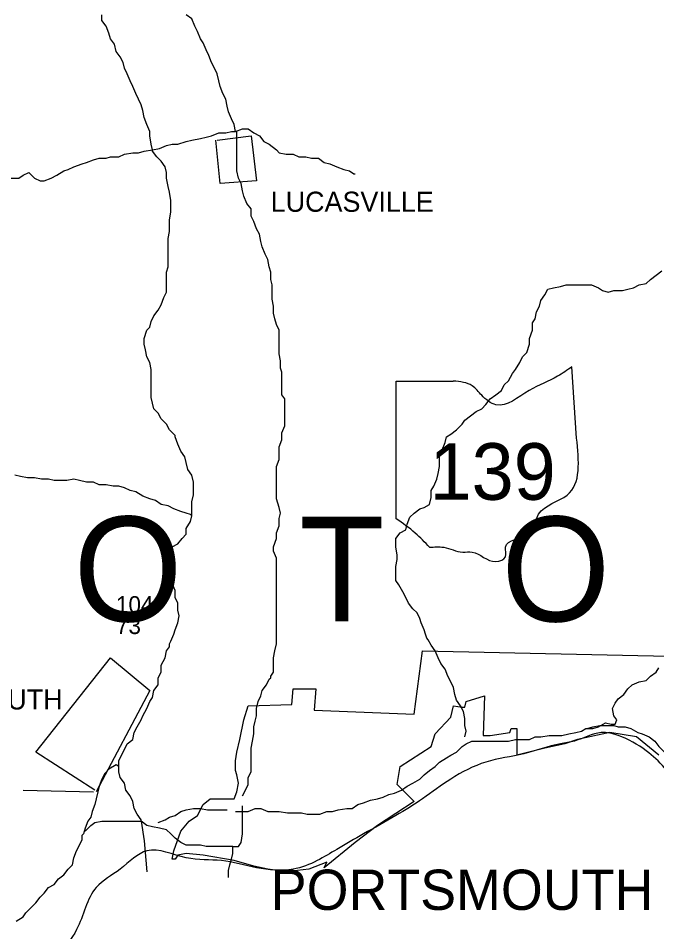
# Model space of a CAD drawing. Extents: x 0 to 34, y 0 to 22.
# Drawn here: x 5.85 to 6.469, y 16.374 to 17.259 of the extents above; entities that cross this region are included whole.
import ezdxf

# ---------------------------------------------------------------- set-up
doc = ezdxf.new("R2010")
doc.units = 0
doc.layers.add('Default', color=7, linetype='Continuous')
doc.layers.add('TR_Turning_Path1', color=7, linetype='Continuous')

msp = doc.modelspace()

# ---------------------------------------------------------------- linework, layer by layer
at = {"layer": 'Default'}
msp.add_line((5.85492, 16.51101), (5.92309, 16.50964), dxfattribs=at)
for points in [[(5.9749, 17.1559), (5.97217, 17.16272), (5.97081, 17.16954), (5.96944, 17.17499), (5.96672, 17.18045), (5.96399, 17.1859), (5.96126, 17.19272), (5.95854, 17.19817), (5.95581, 17.20499), (5.95308, 17.21044), (5.95172, 17.2159), (5.94899, 17.22135), (5.9449, 17.2268), (5.94354, 17.23362), (5.93945, 17.23907), (5.93809, 17.24453), (5.93536, 17.25134), (5.93127, 17.2568), (5.93127, 17.26225)], [(6.06079, 17.14909), (6.05943, 17.1559), (6.0567, 17.16136), (6.05398, 17.16818), (6.05261, 17.17363), (6.05125, 17.18045), (6.04852, 17.1859), (6.0458, 17.19272), (6.04443, 17.19817), (6.04307, 17.20499), (6.04034, 17.21044), (6.03762, 17.2159), (6.03489, 17.22271), (6.03216, 17.22817), (6.02944, 17.23498), (6.02671, 17.23907), (6.02398, 17.24589), (6.02125, 17.25134), (6.01853, 17.25816), (6.01307, 17.26225)], [(5.98035, 17.13136), (5.97899, 17.13682), (5.97763, 17.145), (5.97763, 17.14909), (5.9749, 17.1559), (5.9749, 17.1559)], [(5.98035, 17.13136), (5.98717, 17.13273), (5.99399, 17.13545), (5.99944, 17.13682), (6.00489, 17.13682), (6.01307, 17.13954), (6.01853, 17.14091), (6.02671, 17.14227), (6.03216, 17.14363), (6.03762, 17.145), (6.04443, 17.14772), (6.05125, 17.14772), (6.0567, 17.14909), (6.06079, 17.14909)], [(6.06079, 17.14909), (6.06761, 17.15181), (6.07306, 17.15181), (6.07852, 17.14772), (6.08397, 17.145), (6.08806, 17.13954), (6.09352, 17.13682), (6.10033, 17.13136), (6.10306, 17.12864), (6.10988, 17.12727), (6.11669, 17.12727), (6.12215, 17.12455), (6.12896, 17.12455), (6.13442, 17.12318), (6.14124, 17.12318), (6.14669, 17.11909), (6.15214, 17.11773), (6.15896, 17.115), (6.16578, 17.11228), (6.17123, 17.11091), (6.17532, 17.10818), (6.17668, 17.10818)], [(6.10306, 16.95003), (6.10306, 16.95685), (6.10033, 16.9623), (6.09897, 16.96775), (6.09761, 16.97321), (6.09761, 16.98002), (6.09624, 16.98684), (6.09624, 16.99366), (6.09624, 17.00047), (6.09488, 17.00593), (6.09488, 17.01275), (6.09352, 17.0182), (6.09215, 17.02502), (6.08943, 17.03047), (6.0867, 17.03729), (6.08534, 17.04274), (6.08397, 17.04956), (6.08125, 17.05501), (6.07852, 17.06183), (6.07579, 17.06728), (6.07579, 17.0741), (6.0717, 17.07955), (6.06897, 17.08637), (6.06761, 17.09182), (6.06625, 17.09864), (6.06352, 17.10409), (6.06216, 17.11091), (6.06216, 17.115), (6.06216, 17.12318), (6.06216, 17.12864), (6.06216, 17.13545), (6.06216, 17.14227), (6.06216, 17.14772), (6.06216, 17.14909), (6.06079, 17.14909)], [(6.04307, 17.14091), (6.07579, 17.145), (6.08125, 17.10137), (6.0458, 17.09864), (6.04171, 17.14091)], [(5.84265, 17.10409), (5.85083, 17.10409), (5.85492, 17.10682), (5.86037, 17.10955), (5.86582, 17.10409), (5.87128, 17.10137), (5.87537, 17.10137), (5.88219, 17.10409), (5.88764, 17.10682), (5.89446, 17.11091), (5.89855, 17.11228), (5.904, 17.115), (5.91218, 17.11773), (5.91627, 17.11909), (5.92309, 17.12182), (5.92854, 17.12318), (5.93536, 17.12318), (5.93945, 17.12455), (5.94763, 17.12455), (5.95308, 17.12727), (5.96126, 17.12864), (5.96672, 17.12864), (5.97217, 17.13), (5.98035, 17.13136), (5.98035, 17.13136)], [(5.97763, 16.95957), (5.97899, 16.96503), (5.98172, 16.97048), (5.98581, 16.97593), (5.98853, 16.98139), (5.99126, 16.9882), (5.99399, 16.99366), (5.99399, 17.00047), (5.99399, 17.00593), (5.99399, 17.01275), (5.99535, 17.0182), (5.99535, 17.02502), (5.99535, 17.03183), (5.99535, 17.03865), (5.99535, 17.04547), (5.99671, 17.05228), (5.99671, 17.05774), (5.99671, 17.06319), (5.99808, 17.07137), (5.99808, 17.07819), (5.99808, 17.08228), (5.99671, 17.09046), (5.99535, 17.09591), (5.99399, 17.10409), (5.99399, 17.10955), (5.99262, 17.115), (5.98853, 17.12046), (5.98444, 17.12455), (5.98035, 17.13), (5.98035, 17.13136), (5.98035, 17.13136)], [(6.4221, 16.99366), (6.42755, 16.99502), (6.43573, 16.99502), (6.44119, 16.99638), (6.44664, 16.99775), (6.4521, 17.00047), (6.45891, 17.00184), (6.463, 17.00593), (6.46846, 17.01002), (6.47391, 17.01411)], [(6.34575, 16.94321), (6.34575, 16.94866), (6.34848, 16.95685), (6.34848, 16.96366), (6.3512, 16.96775), (6.35257, 16.97457), (6.35529, 16.98002), (6.35666, 16.98548), (6.36075, 16.99093), (6.36347, 16.99638), (6.36893, 16.99775), (6.37574, 16.99911), (6.3812, 17.00047), (6.38801, 17.00047), (6.39483, 17.00047), (6.40029, 17.00047), (6.40574, 17.00047), (6.41256, 16.99775), (6.41665, 16.99502), (6.4221, 16.99366), (6.4221, 16.99366)], [(6.00217, 16.85459), (5.99671, 16.86004), (5.99399, 16.8655), (5.98853, 16.87095), (5.98581, 16.8764), (5.98172, 16.88049), (5.98035, 16.88595), (5.97899, 16.8914), (5.97899, 16.89958), (5.97899, 16.9064), (5.97899, 16.91185), (5.97899, 16.91867), (5.97763, 16.92549), (5.9749, 16.93094), (5.97353, 16.93776), (5.97217, 16.94321), (5.97217, 16.94866), (5.9749, 16.95685), (5.97763, 16.95957)], [(6.10033, 16.79323), (6.10033, 16.80005), (6.10033, 16.80551), (6.10033, 16.81232), (6.10033, 16.81778), (6.10033, 16.82459), (6.10306, 16.83141), (6.10306, 16.83686), (6.10306, 16.84368), (6.10579, 16.8505), (6.10579, 16.85732), (6.10851, 16.86413), (6.10851, 16.86959), (6.10851, 16.87504), (6.10851, 16.88322), (6.10851, 16.89004), (6.10579, 16.89413), (6.10579, 16.90231), (6.10579, 16.90776), (6.10579, 16.91594), (6.10442, 16.92003), (6.10442, 16.92685), (6.10306, 16.93367), (6.10306, 16.94048), (6.10306, 16.9473), (6.10306, 16.94866), (6.10306, 16.95003)], [(6.26122, 16.84095), (6.26394, 16.84777), (6.26531, 16.85323), (6.2694, 16.85595), (6.27485, 16.86004), (6.2803, 16.8655), (6.28303, 16.86959), (6.28849, 16.87368), (6.29394, 16.87777), (6.29939, 16.88049), (6.30348, 16.88458), (6.30757, 16.89004), (6.31303, 16.89413), (6.31848, 16.89822), (6.32121, 16.90367), (6.3253, 16.90776), (6.32939, 16.91458), (6.33211, 16.91867), (6.3362, 16.92549), (6.33893, 16.93094), (6.34302, 16.93503), (6.34575, 16.94321), (6.34575, 16.94321)], [(6.39142, 16.8522), (6.38682, 16.92123)], [(6.21656, 16.77398), (6.21656, 16.90742), (6.27178, 16.90742)], [(6.01853, 16.77687), (6.01853, 16.78369), (6.01853, 16.79051), (6.01989, 16.79733), (6.01989, 16.80414), (6.01989, 16.8096), (6.01853, 16.81641), (6.01444, 16.82187), (6.01307, 16.82868), (6.01171, 16.83414), (6.00762, 16.83959), (6.00489, 16.84641), (6.00217, 16.85323), (6.00217, 16.85323), (6.00217, 16.85459)], [(6.21622, 16.75506), (6.22031, 16.76051), (6.22577, 16.76324), (6.22713, 16.76869), (6.22986, 16.77551), (6.23395, 16.7796), (6.2394, 16.78369), (6.24349, 16.78505), (6.24895, 16.78778), (6.25031, 16.7946), (6.25031, 16.80142), (6.25304, 16.80551), (6.25576, 16.81232), (6.25713, 16.81778), (6.25849, 16.82459), (6.25849, 16.82868), (6.25849, 16.83686), (6.26122, 16.83959), (6.26122, 16.84095)], [(6.01853, 16.77687), (6.01716, 16.77824), (6.01307, 16.7796), (6.00762, 16.78096), (6.0008, 16.78369), (5.99535, 16.78642), (5.98853, 16.78778), (5.98308, 16.79187), (5.97763, 16.79323), (5.97081, 16.79596), (5.96399, 16.80005), (5.95854, 16.80142), (5.95308, 16.80414), (5.94763, 16.80551), (5.94218, 16.80551), (5.93536, 16.80687), (5.92854, 16.80687), (5.92309, 16.8096), (5.91627, 16.8096), (5.90945, 16.81096), (5.904, 16.81232), (5.89718, 16.81096), (5.89037, 16.81096), (5.88491, 16.81096), (5.87946, 16.81232), (5.87264, 16.81232), (5.86582, 16.81369), (5.85901, 16.81369), (5.85219, 16.81505), (5.84674, 16.81641)], [(6.09488, 16.62144), (6.09761, 16.62553), (6.09761, 16.63235), (6.09761, 16.63917), (6.09897, 16.64599), (6.10033, 16.6528), (6.10033, 16.65826), (6.10033, 16.66507), (6.10033, 16.67053), (6.10033, 16.67734), (6.10033, 16.68416), (6.10033, 16.68961), (6.10033, 16.6978), (6.10033, 16.70325), (6.10033, 16.71007), (6.10033, 16.71416), (6.10033, 16.72234), (6.10033, 16.72779), (6.10033, 16.73597), (6.09761, 16.74279), (6.09761, 16.74688), (6.10033, 16.75506), (6.10033, 16.76051), (6.10306, 16.76733), (6.10306, 16.77415), (6.10442, 16.7796), (6.10306, 16.78505), (6.10033, 16.79323)], [(5.99671, 16.65008), (5.99671, 16.6528), (5.99808, 16.65553), (6.0008, 16.66235), (6.00217, 16.66644), (6.00489, 16.67325), (6.00626, 16.68007), (6.00489, 16.68552), (6.00489, 16.69234), (6.00217, 16.6978), (6.00217, 16.70461), (5.99944, 16.71143), (5.99808, 16.71688), (5.99671, 16.72234), (5.99535, 16.72915), (5.99535, 16.73597), (5.99535, 16.74279), (5.99944, 16.74688), (6.00489, 16.74961), (6.00898, 16.75506), (6.01307, 16.75915), (6.01307, 16.7646), (6.01716, 16.77142), (6.01853, 16.77687)], [(5.99671, 16.65008), (5.99671, 16.6528), (5.99808, 16.65553), (6.0008, 16.66235), (6.00217, 16.66644), (6.00489, 16.67325), (6.00626, 16.68007), (6.00489, 16.68552), (6.00489, 16.69234), (6.00217, 16.6978), (6.00217, 16.70461), (5.99944, 16.71143), (5.99808, 16.71688), (5.99671, 16.72234), (5.99535, 16.72915), (5.99535, 16.73597), (5.99535, 16.74279), (5.99944, 16.74688), (6.00489, 16.74961), (6.00898, 16.75506), (6.01307, 16.75915), (6.01307, 16.7646), (6.01716, 16.77142), (6.01853, 16.77687)], [(6.24486, 16.66235), (6.24349, 16.66644), (6.24077, 16.67325), (6.2394, 16.67734), (6.23668, 16.6828), (6.23258, 16.68689), (6.22849, 16.69234), (6.22577, 16.6978), (6.22304, 16.70325), (6.21895, 16.71007), (6.21622, 16.71416), (6.21622, 16.72097), (6.21622, 16.72779), (6.21759, 16.73461), (6.21759, 16.7387), (6.21622, 16.74688), (6.21622, 16.75233), (6.21622, 16.75506)], [(6.28303, 16.56282), (6.28439, 16.56827), (6.28303, 16.57372), (6.28303, 16.58054), (6.28167, 16.58736), (6.27894, 16.59281), (6.27485, 16.59827), (6.27349, 16.60372), (6.27212, 16.61054), (6.2694, 16.61599), (6.26667, 16.62144), (6.26394, 16.62826), (6.25985, 16.63371), (6.25713, 16.63917), (6.2544, 16.64599), (6.25031, 16.65144), (6.24758, 16.65689), (6.24622, 16.65826), (6.24486, 16.66235)], [(5.94763, 16.53418), (5.94763, 16.53555), (5.94763, 16.53964), (5.95036, 16.54509), (5.95308, 16.55055), (5.95581, 16.556), (5.96126, 16.56009), (5.96263, 16.56691), (5.96535, 16.57236), (5.96944, 16.57918), (5.97081, 16.58327), (5.9749, 16.59009), (5.97763, 16.5969), (5.98035, 16.60099), (5.98172, 16.60781), (5.98581, 16.61326), (5.98581, 16.62008), (5.98853, 16.62553), (5.98853, 16.63235), (5.99262, 16.63917), (5.99399, 16.64599), (5.99671, 16.65008)], [(5.94763, 16.53418), (5.94763, 16.53555), (5.94763, 16.53964), (5.95036, 16.54509), (5.95308, 16.55055), (5.95581, 16.556), (5.96126, 16.56009), (5.96263, 16.56691), (5.96535, 16.57236), (5.96944, 16.57918), (5.97081, 16.58327), (5.9749, 16.59009), (5.97763, 16.5969), (5.98035, 16.60099), (5.98172, 16.60781), (5.98581, 16.61326), (5.98581, 16.62008), (5.98853, 16.62553), (5.98853, 16.63235), (5.99262, 16.63917), (5.99399, 16.64599), (5.99671, 16.65008)], [(6.0008, 16.45238), (6.00762, 16.47147), (6.0158, 16.48101), (6.02398, 16.48647), (6.02944, 16.49737), (6.03625, 16.50283), (6.05943, 16.50283), (6.06216, 16.50964), (6.06352, 16.51782), (6.06216, 16.526), (6.06079, 16.53009), (6.06079, 16.53964), (6.06216, 16.54782), (6.06488, 16.56009), (6.06897, 16.57918), (6.07306, 16.59281), (6.11533, 16.59418), (6.11669, 16.60917), (6.13851, 16.60917), (6.13715, 16.58872), (6.23395, 16.58463), (6.24213, 16.64599), (6.49573, 16.64053)], [(5.92445, 16.51101), (5.86719, 16.54782), (5.93945, 16.63917), (5.97763, 16.60781), (5.92582, 16.50964)], [(6.42892, 16.57509), (6.43028, 16.57918), (6.42755, 16.58327), (6.42619, 16.59009), (6.42892, 16.59554), (6.43164, 16.59963), (6.4371, 16.60372), (6.44119, 16.60917), (6.44528, 16.61326), (6.4521, 16.61599), (6.45891, 16.61735), (6.463, 16.62144), (6.46846, 16.62553), (6.47118, 16.62962)], [(6.07579, 16.53282), (6.07579, 16.53964), (6.07579, 16.54646), (6.07579, 16.55191), (6.07715, 16.55873), (6.07852, 16.56554), (6.07852, 16.57236), (6.07988, 16.57781), (6.08125, 16.58327), (6.08125, 16.59009), (6.08261, 16.5969), (6.08534, 16.60236), (6.0867, 16.60781), (6.09079, 16.61326), (6.09352, 16.61872), (6.09488, 16.62008), (6.09488, 16.62144)], [(6.23395, 16.5001), (6.21759, 16.51646), (6.22031, 16.53418), (6.25031, 16.55327), (6.2544, 16.56554), (6.2694, 16.5819), (6.27212, 16.59281), (6.2803, 16.59145), (6.28303, 16.59145), (6.28439, 16.5969), (6.30212, 16.60236), (6.30076, 16.56418), (6.30757, 16.56418), (6.32666, 16.56691), (6.32802, 16.571), (6.33348, 16.571), (6.33348, 16.54509)], [(6.40165, 16.571), (6.4071, 16.571), (6.41256, 16.57236), (6.41937, 16.57645), (6.42483, 16.57509), (6.42892, 16.57509)], [(6.40165, 16.571), (6.4071, 16.57236), (6.41392, 16.57372), (6.41937, 16.57372), (6.42755, 16.57372), (6.43164, 16.57236), (6.43846, 16.57236), (6.44392, 16.571), (6.45073, 16.56691), (6.45482, 16.56554), (6.46164, 16.56282), (6.46709, 16.55873), (6.47118, 16.55327), (6.47664, 16.54782), (6.47664, 16.54782)], [(6.31303, 16.55873), (6.31848, 16.55873), (6.3253, 16.55873), (6.33211, 16.56009), (6.33893, 16.56009), (6.34575, 16.56009), (6.3512, 16.56282), (6.35666, 16.56282), (6.36484, 16.56418), (6.37029, 16.56418), (6.37711, 16.56418), (6.38392, 16.56554), (6.39074, 16.56691), (6.3962, 16.56827), (6.40029, 16.571), (6.40165, 16.571)], [(6.47118, 16.54509), (6.44937, 16.56282), (6.42346, 16.56691), (6.39211, 16.56009), (6.37983, 16.556), (6.36075, 16.55191), (6.33348, 16.54509)], [(6.19168, 16.50146), (6.1985, 16.50283), (6.20395, 16.50419), (6.20941, 16.50692), (6.21486, 16.50828), (6.22168, 16.51101), (6.22713, 16.5151), (6.23258, 16.51782), (6.2394, 16.52191), (6.24349, 16.526), (6.24895, 16.53009), (6.2544, 16.53418), (6.25849, 16.53828), (6.26531, 16.54237), (6.2694, 16.54509), (6.27485, 16.54782), (6.2803, 16.55327), (6.28439, 16.556), (6.28985, 16.55873), (6.28985, 16.55873)], [(6.28985, 16.55873), (6.29667, 16.55873), (6.30348, 16.55873), (6.3103, 16.55873), (6.31303, 16.55873)], [(5.94763, 16.53418), (5.94763, 16.53418), (5.9449, 16.53555), (5.93809, 16.53146), (5.934, 16.52737), (5.93127, 16.52191), (5.92854, 16.5151), (5.92718, 16.50964), (5.92582, 16.50283), (5.92445, 16.49737), (5.92172, 16.49056), (5.92036, 16.4851)], [(5.96944, 16.48101), (5.96944, 16.48237), (5.96535, 16.48783), (5.96263, 16.49328), (5.96126, 16.5001), (5.95854, 16.50555), (5.95445, 16.51101), (5.95308, 16.51782), (5.94899, 16.52328), (5.94763, 16.52873), (5.94763, 16.53418)], [(5.96944, 16.48101), (5.96944, 16.48237), (5.96535, 16.48783), (5.96263, 16.49328), (5.96126, 16.5001), (5.95854, 16.50555), (5.95445, 16.51101), (5.95308, 16.51782), (5.94899, 16.52328), (5.94763, 16.52873), (5.94763, 16.53418)], [(6.06761, 16.50555), (6.07034, 16.51101), (6.07306, 16.51646), (6.07306, 16.52328), (6.07579, 16.52873), (6.07579, 16.53282)], [(6.23395, 16.5001), (6.1985, 16.47692), (6.17668, 16.46056), (6.14669, 16.43602), (6.14942, 16.44147), (6.13169, 16.43466), (6.10988, 16.43193), (6.09215, 16.43466), (6.07852, 16.43738), (6.05943, 16.44284), (6.02944, 16.44829), (6.01307, 16.44965), (6.00489, 16.44829), (6.00217, 16.4442)], [(6.06761, 16.49056), (6.06761, 16.49601)], [(6.15487, 16.49056), (6.16032, 16.49192), (6.1685, 16.49328), (6.17396, 16.49328), (6.17941, 16.49737), (6.18487, 16.49874), (6.19168, 16.50146)], [(5.92036, 16.4851), (5.91763, 16.48101), (5.91491, 16.47419), (5.91354, 16.46874)], [(5.98581, 16.47965), (5.99262, 16.48237), (5.99671, 16.4851), (6.00217, 16.48647), (6.00762, 16.49056), (6.01307, 16.49192), (6.01989, 16.49328), (6.02671, 16.49328), (6.03353, 16.49192), (6.03898, 16.49192), (6.0458, 16.49192), (6.05125, 16.49192), (6.05261, 16.49192)], [(6.05807, 16.45647), (6.06352, 16.45647), (6.06625, 16.46056), (6.06761, 16.46874), (6.06761, 16.47419), (6.06761, 16.48101), (6.06761, 16.48647), (6.06761, 16.49056)], [(6.06079, 16.49056), (6.06761, 16.49056), (6.06761, 16.49056)], [(6.06761, 16.49056), (6.07306, 16.49056), (6.07988, 16.49328), (6.08534, 16.49328), (6.09215, 16.49056), (6.09761, 16.49056), (6.10306, 16.49056), (6.11124, 16.48919), (6.11669, 16.48919), (6.12487, 16.48919), (6.13033, 16.48783), (6.13715, 16.48783), (6.1426, 16.48783), (6.14942, 16.49056), (6.15214, 16.49056), (6.15487, 16.49056)], [(5.91491, 16.47147), (5.92036, 16.47692), (5.92445, 16.47965), (5.93127, 16.48101), (5.93809, 16.48101), (5.9449, 16.48101), (5.94899, 16.48101), (5.95581, 16.48101), (5.96263, 16.48101), (5.96944, 16.48101), (5.96944, 16.48101)], [(6.05807, 16.45647), (6.0567, 16.45647), (6.05261, 16.45647), (6.0458, 16.45647), (6.03898, 16.45647), (6.03216, 16.45647), (6.02671, 16.45783), (6.01989, 16.45783), (6.01307, 16.45783), (6.00762, 16.46056), (6.00217, 16.46465), (5.99808, 16.46874), (5.99399, 16.47283), (5.98717, 16.47419), (5.98035, 16.47556), (5.9749, 16.47692), (5.96944, 16.48101)], [(6.05807, 16.45647), (6.0567, 16.45647), (6.05261, 16.45647), (6.0458, 16.45647), (6.03898, 16.45647), (6.03216, 16.45647), (6.02671, 16.45783), (6.01989, 16.45783), (6.01307, 16.45783), (6.00762, 16.46056), (6.00217, 16.46465), (5.99808, 16.46874), (5.99399, 16.47283), (5.98717, 16.47419), (5.98035, 16.47556), (5.9749, 16.47692), (5.96944, 16.48101)], [(5.96944, 16.48101), (5.97217, 16.46192), (5.9749, 16.43193)], [(5.8481, 16.38421), (5.85492, 16.3883), (5.85764, 16.39239), (5.8631, 16.39784), (5.86719, 16.40193), (5.87128, 16.40739), (5.87537, 16.41148), (5.87946, 16.41693), (5.88491, 16.41966), (5.889, 16.42511), (5.89446, 16.4292), (5.89855, 16.43466), (5.90264, 16.43875), (5.904, 16.44556), (5.90673, 16.45238), (5.90945, 16.45783), (5.91218, 16.46329), (5.91218, 16.46738), (5.91354, 16.46874)], [(6.00217, 16.4442), (5.99944, 16.4442), (6.0008, 16.45238)], [(6.0567, 16.4442), (6.05807, 16.44965), (6.05807, 16.45647)], [(6.05398, 16.42647), (6.05398, 16.43329), (6.05534, 16.43875), (6.0567, 16.4442), (6.0567, 16.4442)]]:
    msp.add_lwpolyline(points, dxfattribs=at)
for points in [[(6.38682, 16.92123), (6.37302, 16.91202), (6.34541, 16.89822), (6.3132, 16.88441), (6.29939, 16.89362), (6.29019, 16.90282), (6.27178, 16.90742)], [(6.24878, 16.74637), (6.26258, 16.74637), (6.28099, 16.74177), (6.29019, 16.74177), (6.3132, 16.73256), (6.3224, 16.73716), (6.3224, 16.74637), (6.34541, 16.76017), (6.35461, 16.77858), (6.38222, 16.79698), (6.39142, 16.8522)], [(6.24878, 16.74637), (6.23497, 16.76017), (6.21656, 16.77398)], [(6.69478, 15.72431), (6.66479, 15.7434), (6.64025, 15.76249), (6.60889, 15.78703), (6.58844, 15.82384), (6.5748, 15.85929), (6.56253, 15.89065), (6.55299, 15.93701), (6.54754, 15.97655), (6.54754, 16.01881), (6.54754, 16.05699), (6.54481, 16.1088), (6.53117, 16.1497), (6.52027, 16.18379), (6.50391, 16.20969), (6.48754, 16.22878), (6.47936, 16.25605), (6.47936, 16.29831), (6.493, 16.33376), (6.50254, 16.37603), (6.50254, 16.41966), (6.49573, 16.46192), (6.493, 16.50283), (6.47664, 16.53282), (6.45891, 16.54918), (6.43164, 16.56418), (6.41528, 16.56691), (6.38938, 16.55873), (6.37574, 16.556), (6.3403, 16.54646), (6.30348, 16.53828), (6.2694, 16.52191), (6.24213, 16.50283), (6.21622, 16.48647), (6.18487, 16.46874), (6.15896, 16.45374), (6.13987, 16.44284), (6.11669, 16.43466), (6.08125, 16.43602), (6.04716, 16.44284), (6.01307, 16.44556), (5.9749, 16.45238), (5.94899, 16.43466), (5.92582, 16.41693), (5.90673, 16.37603), (5.889, 16.35149), (5.86582, 16.31604), (5.84674, 16.28195), (5.82356, 16.27241), (5.78402, 16.25605), (5.7513, 16.23969), (5.71039, 16.22742), (5.68313, 16.21242), (5.64631, 16.19606), (5.6245, 16.16606), (5.61223, 16.14152), (5.59859, 16.10607), (5.58905, 16.07199), (5.58632, 16.03108), (5.55496, 16.00245), (5.52088, 15.97655), (5.47316, 15.95337), (5.42271, 15.95337), (5.38181, 15.94519), (5.33682, 15.94519), (5.29319, 15.95064), (5.25229, 15.96973), (5.22638, 15.98745), (5.19229, 15.99427), (5.16639, 15.99563), (5.14867, 15.97927), (5.11458, 15.96837), (5.0914, 15.95064)]]:
    msp.add_spline(points, degree=3, dxfattribs=at)

# ---------------------------------------------------------------- texts
for s, height, p in [('LUCASVILLE', 0.019502, (6.09488, 17.07137)), ('139', 0.05486, (6.24878, 16.79238)), ('104', 0.016255, (5.9449, 16.6828)), ('73', 0.016255, (5.9449, 16.66235)), ('PORTSMOUTH', 0.019502, (5.70767, 16.58926)), ('PORTSMOUTH', 0.039005, (6.09488, 16.39512))]:
    msp.add_text(s, height=height, dxfattribs=at).set_placement(p)
at = {"layer": 'TR_Turning_Path1'}
msp.add_text('S   C   I   O   T   O', height=0.1014887, dxfattribs=at).set_placement((5.33818, 16.67462))

doc.saveas('drawing.dxf')
